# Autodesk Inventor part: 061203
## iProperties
Company: CADCIM Technologies
Shininess: 64.0
Length Units: 11269
Angle Units: 11279
Time Units: 11290
Mass Units: 11283
Length Display Precision: 3
Angle Display Precision: 2
Compacted: True
Part Number: 061203
Document SubType Name: Modeling
Created: 2002-12
Designer: deepak
Description: Sample Drawing
Engineer: Deepak
Vendor: CADSoft
Density: 1 g/cm^3
Density: 0.0
Volumn: 0.0
Area: 0.0
PropertySet Name: Model Information
Control State: 0
Master: False
Checked Out: False
Author: deepak
Title: Aligned Section
Revision Number: 4
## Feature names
1. Revolution1
2. Hole1
3. Extrusion1
4. Hole2
5. Circular Pattern1
